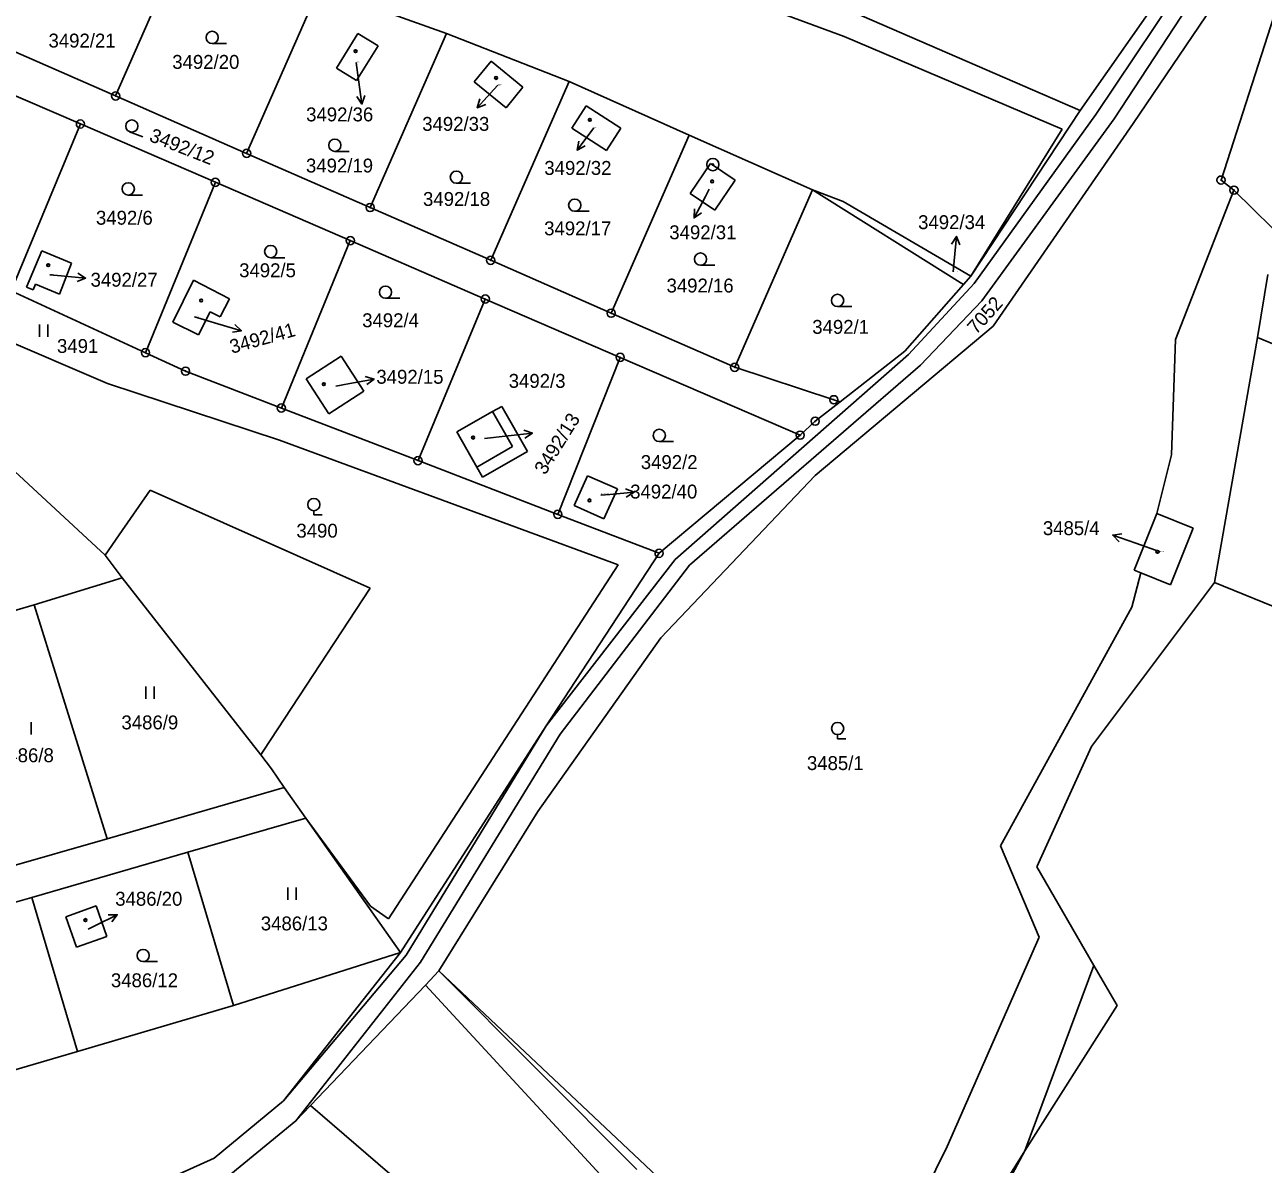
# Model space of a CAD drawing. Extents: x -593183 to -588034, y -1130415 to -1124994.
# Drawn here: x -592719.7 to -592568.1, y -1129131.8 to -1128992.3 of the extents above; entities that cross this region are included whole.
import ezdxf

# ---------------------------------------------------------------- set-up
doc = ezdxf.new("R2010")
doc.units = 0
for name, color, linetype in [('Vrstva 1', 7, 'Continuous'), ('Vrstva 16', 7, 'Continuous'), ('Vrstva 18', 7, 'Continuous'), ('Vrstva 19', 7, 'Continuous'), ('Vrstva 24', 7, 'Continuous'), ('Vrstva 25', 7, 'Continuous'), ('Vrstva 4', 7, 'Continuous')]:
    doc.layers.add(name, color=color, linetype=linetype)

msp = doc.modelspace()

# ---------------------------------------------------------------- linework, layer by layer
at = {"layer": 'Vrstva 1'}
for p, q in [((-592573.29, -1129011.33), (-592560.53, -1128971.61)), ((-592700.22, -1128981.88), (-592708.62, -1129001.03)), ((-592568.79, -1128981.77), (-592584.04, -1129004.42)), ((-592639.27, -1128986.41), (-592619.45, -1128993.77)), ((-592579.11, -1128986.5), (-592590.56, -1129002.83)), ((-592683.7, -1128987.81), (-592692.58, -1129008.06)), ((-592683.7, -1128987.81), (-592668.12, -1128993.38)), ((-592590.56, -1129002.83), (-592619.43, -1128990.29)), ((-592725.11, -1128993.8), (-592708.62, -1129001.03)), ((-592681.59, -1128997.61), (-592678.96, -1128993.4)), ((-592678.96, -1128993.4), (-592676.49, -1128994.89)), ((-592668.12, -1128993.38), (-592677.46, -1129014.69)), ((-592668.12, -1128993.38), (-592653.1, -1128999.25)), ((-592619.45, -1128993.77), (-592592.73, -1129005.09)), ((-592676.49, -1128994.89), (-592679.15, -1128999.14)), ((-592664.71, -1128999.29), (-592662.66, -1128996.78)), ((-592662.66, -1128996.78), (-592658.76, -1128999.97)), ((-592728.81, -1128997.59), (-592712.93, -1129004.46)), ((-592679.15, -1128999.14), (-592681.59, -1128997.61)), ((-592660.81, -1129002.48), (-592664.71, -1128999.29)), ((-592662.7, -1129021.15), (-592653.1, -1128999.25)), ((-592658.76, -1128999.97), (-592660.81, -1129002.48)), ((-592653.1, -1128999.25), (-592638.39, -1129005.81)), ((-592708.62, -1129001.03), (-592692.58, -1129008.06)), ((-592652.78, -1129004.97), (-592651.02, -1129002.24)), ((-592651.02, -1129002.24), (-592646.78, -1129004.98)), ((-592590.56, -1129002.83), (-592603.91, -1129023.08)), ((-592712.93, -1129004.46), (-592721.41, -1129024.9)), ((-592712.93, -1129004.46), (-592696.41, -1129011.6)), ((-592601.18, -1129029.23), (-592584.04, -1129004.42)), ((-592648.54, -1129007.71), (-592652.78, -1129004.97)), ((-592646.78, -1129004.98), (-592648.54, -1129007.71)), ((-592638.39, -1129005.81), (-592647.95, -1129027.62)), ((-592638.39, -1129005.81), (-592623.31, -1129012.53)), ((-592603.91, -1129023.08), (-592592.73, -1129005.09)), ((-592692.58, -1129008.06), (-592677.46, -1129014.69)), ((-592638.28, -1129012.98), (-592635.8, -1129009.3)), ((-592635.8, -1129009.3), (-592632.79, -1129011.33)), ((-592696.41, -1129011.6), (-592704.97, -1129032.46)), ((-592696.41, -1129011.6), (-592679.89, -1129018.74)), ((-592632.79, -1129011.33), (-592635.27, -1129015.01)), ((-592573.29, -1129011.33), (-592571.71, -1129012.56)), ((-592635.27, -1129015.01), (-592638.28, -1129012.98)), ((-592632.83, -1129034.25), (-592623.31, -1129012.53)), ((-592623.31, -1129012.53), (-592619.56, -1129013.97)), ((-592623.31, -1129012.53), (-592605.24, -1129023.85)), ((-592619.56, -1129013.97), (-592603.91, -1129023.08)), ((-592571.71, -1129012.56), (-592564.45, -1129019.72)), ((-592677.46, -1129014.69), (-592662.7, -1129021.15)), ((-592719.52, -1129024.44), (-592717.66, -1129019.99)), ((-592717.66, -1129019.99), (-592714.04, -1129021.5)), ((-592679.89, -1129018.74), (-592688.33, -1129039.23)), ((-592679.89, -1129018.74), (-592663.37, -1129025.89)), ((-592714.04, -1129021.5), (-592715.5, -1129025.29)), ((-592662.7, -1129021.15), (-592647.95, -1129027.62)), ((-592604.82, -1129024.11), (-592603.91, -1129023.08)), ((-592567.57, -1129022.9), (-592568.85, -1129030.58)), ((-592718.7, -1129024.78), (-592719.52, -1129024.44)), ((-592718.41, -1129024.08), (-592718.7, -1129024.78)), ((-592715.5, -1129025.29), (-592718.41, -1129024.08)), ((-592701.63, -1129028.71), (-592699.09, -1129023.6)), ((-592699.09, -1129023.6), (-592694.7, -1129025.87)), ((-592604.82, -1129024.11), (-592612.02, -1129032.27)), ((-592605.24, -1129023.85), (-592604.82, -1129024.11)), ((-592704.97, -1129032.46), (-592721.41, -1129024.9)), ((-592694.7, -1129025.87), (-592695.82, -1129028.08)), ((-592663.37, -1129025.89), (-592671.6, -1129045.67)), ((-592663.37, -1129025.89), (-592646.85, -1129033.03)), ((-592697.06, -1129027.46), (-592698.48, -1129030.29)), ((-592695.82, -1129028.08), (-592697.06, -1129027.46)), ((-592647.95, -1129027.62), (-592632.83, -1129034.25)), ((-592698.48, -1129030.29), (-592701.63, -1129028.71)), ((-592723.17, -1129030.44), (-592709.6, -1129036.24)), ((-592622.99, -1129047.5), (-592601.18, -1129029.23)), ((-592568.85, -1129030.58), (-592574.1, -1129060.59)), ((-592568.85, -1129030.58), (-592498.73, -1129059.92)), ((-592700.06, -1129034.72), (-592704.97, -1129032.46)), ((-592685.31, -1129035.67), (-592681.03, -1129032.87)), ((-592681.03, -1129032.87), (-592678.23, -1129037.15)), ((-592646.85, -1129033.03), (-592654.49, -1129052.25)), ((-592646.85, -1129033.03), (-592624.82, -1129042.56)), ((-592619.94, -1129038.47), (-592612.02, -1129032.27)), ((-592700.06, -1129034.72), (-592688.33, -1129039.23)), ((-592632.83, -1129034.25), (-592620.7, -1129038.22)), ((-592709.6, -1129036.24), (-592688.56, -1129043.17)), ((-592682.51, -1129039.95), (-592685.31, -1129035.67)), ((-592678.23, -1129037.15), (-592682.51, -1129039.95)), ((-592620.7, -1129038.22), (-592619.94, -1129038.47)), ((-592688.33, -1129039.23), (-592671.6, -1129045.67)), ((-592666.85, -1129042.15), (-592662.49, -1129039.67)), ((-592662.49, -1129039.67), (-592661.36, -1129039.03)), ((-592661.36, -1129039.03), (-592658.21, -1129044.56)), ((-592619.94, -1129038.47), (-592622.98, -1129040.85)), ((-592728.65, -1129039.91), (-592709.9, -1129057.25)), ((-592624.82, -1129042.56), (-592622.98, -1129040.85)), ((-592664.4, -1129046.46), (-592666.85, -1129042.15)), ((-592642.09, -1129057.02), (-592624.82, -1129042.56)), ((-592688.56, -1129043.17), (-592647.1, -1129058.41)), ((-592671.6, -1129045.67), (-592654.49, -1129052.25)), ((-592658.21, -1129044.56), (-592663.7, -1129047.68)), ((-592663.7, -1129047.68), (-592664.4, -1129046.46)), ((-592652.5, -1129051.15), (-592650.85, -1129047.52)), ((-592647.18, -1129049.13), (-592650.85, -1129047.52)), ((-592641.86, -1129067.36), (-592622.99, -1129047.5)), ((-592648.85, -1129052.8), (-592647.18, -1129049.13)), ((-592652.5, -1129051.15), (-592648.85, -1129052.8)), ((-592654.49, -1129052.25), (-592642.09, -1129057.02)), ((-592583.95, -1129059.08), (-592581.15, -1129052.15)), ((-592581.15, -1129052.15), (-592576.69, -1129053.95)), ((-592576.69, -1129053.95), (-592579.49, -1129060.88)), ((-592709.9, -1129057.25), (-592707.81, -1129060.01)), ((-592642.09, -1129057.02), (-592655.93, -1129078.12)), ((-592647.1, -1129058.41), (-592675.2, -1129101.76)), ((-592583.11, -1129059.42), (-592583.95, -1129059.08)), ((-592579.49, -1129060.88), (-592583.11, -1129059.42)), ((-592707.81, -1129060.01), (-592718.6, -1129063.31)), ((-592707.81, -1129060.01), (-592690.86, -1129081.7)), ((-592589.17, -1129080.66), (-592574.1, -1129060.59)), ((-592574.1, -1129060.59), (-592554.68, -1129068.54)), ((-592718.6, -1129063.31), (-592731.07, -1129067)), ((-592718.6, -1129063.31), (-592709.67, -1129091.97)), ((-592656.94, -1129088.63), (-592641.86, -1129067.36)), ((-592655.93, -1129078.12), (-592673.76, -1129105.9)), ((-592595.84, -1129095.4), (-592589.17, -1129080.66)), ((-592690.86, -1129081.7), (-592689.53, -1129083.41)), ((-592687.99, -1129085.67), (-592689.53, -1129083.41)), ((-592687.99, -1129085.67), (-592709.67, -1129091.97)), ((-592685.35, -1129089.43), (-592687.99, -1129085.67)), ((-592699.8, -1129093.61), (-592685.35, -1129089.43)), ((-592673.76, -1129105.9), (-592685.35, -1129089.43)), ((-592685.35, -1129089.43), (-592677.42, -1129100.23)), ((-592669.04, -1129108.14), (-592656.94, -1129088.63)), ((-592709.67, -1129091.97), (-592722.19, -1129095.57)), ((-592699.8, -1129093.61), (-592718.88, -1129099.14)), ((-592694.19, -1129112.37), (-592699.8, -1129093.61)), ((-592595.84, -1129095.4), (-592588.85, -1129107.46)), ((-592718.88, -1129099.14), (-592738.2, -1129104.7)), ((-592718.88, -1129099.14), (-592713.27, -1129118.02)), ((-592714.73, -1129101.51), (-592711, -1129100.19)), ((-592711, -1129100.19), (-592709.68, -1129103.92)), ((-592675.2, -1129101.76), (-592677.42, -1129100.23)), ((-592713.41, -1129105.24), (-592714.73, -1129101.51)), ((-592709.68, -1129103.92), (-592713.41, -1129105.24)), ((-592694.19, -1129112.37), (-592673.76, -1129105.9)), ((-592673.76, -1129105.9), (-592688.05, -1129124.05)), ((-592588.85, -1129107.46), (-592597.31, -1129130.16)), ((-592669.04, -1129108.14), (-592670.69, -1129109.87)), ((-592669.04, -1129108.14), (-592619.36, -1129154.88)), ((-592684.77, -1129124.62), (-592670.69, -1129109.87)), ((-592670.69, -1129109.87), (-592647.33, -1129135.19)), ((-592713.27, -1129118.02), (-592694.19, -1129112.37)), ((-592732.76, -1129123.67), (-592713.27, -1129118.02)), ((-592688.05, -1129124.05), (-592696.54, -1129131.05)), ((-592686.57, -1129126.51), (-592684.77, -1129124.62)), ((-592684.77, -1129124.62), (-592650.74, -1129153.85)), ((-592694.96, -1129133.39), (-592686.57, -1129126.51)), ((-592597.31, -1129130.16), (-592613.56, -1129160.33)), ((-592696.54, -1129131.05), (-592715.63, -1129139.64))]:
    msp.add_line(p, q, dxfattribs=at)
at = {"layer": 'Vrstva 16'}
for p, q in [((-592679.18, -1128996.92), (-592678.88, -1128999.05)), ((-592661.84, -1128999.72), (-592662.33, -1129000.25)), ((-592650.09, -1129004.92), (-592650.33, -1129005.24)), ((-592635.95, -1129012.46), (-592636.4, -1129013.32)), ((-592606.07, -1129022.54), (-592605.96, -1129021.22)), ((-592716.68, -1129022.94), (-592715.28, -1129023.06)), ((-592698.98, -1129028.05), (-592696.1, -1129028.91)), ((-592681.66, -1129036.56), (-592679.94, -1129036.24)), ((-592663.45, -1129042.97), (-592660.58, -1129042.65)), ((-592649.21, -1129049.89), (-592648.14, -1129049.8)), ((-592580.74, -1129056.84), (-592583.72, -1129055.79)), ((-592712, -1129103.05), (-592711.1, -1129102.6))]:
    msp.add_line(p, q, dxfattribs=at)
at = {"layer": 'Vrstva 24'}
for centre, radius in [((-592708.62, -1129001.03), 0.5), ((-592708.62, -1129001.03), 0.0327), ((-592712.93, -1129004.46), 0.5), ((-592712.93, -1129004.46), 0.0327), ((-592692.58, -1129008.06), 0.5), ((-592692.58, -1129008.06), 0.0327), ((-592635.51, -1129009.43), 0.75), ((-592635.51, -1129009.43), 0.0903), ((-592573.29, -1129011.33), 0.5), ((-592696.41, -1129011.6), 0.5), ((-592696.41, -1129011.6), 0.0327), ((-592573.29, -1129011.33), 0.0327), ((-592571.71, -1129012.56), 0.5), ((-592571.71, -1129012.56), 0.0327), ((-592677.46, -1129014.69), 0.5), ((-592677.46, -1129014.69), 0.0327), ((-592679.89, -1129018.74), 0.5), ((-592679.89, -1129018.74), 0.0327), ((-592662.7, -1129021.15), 0.5), ((-592662.7, -1129021.15), 0.0327), ((-592663.37, -1129025.89), 0.5), ((-592663.37, -1129025.89), 0.0327), ((-592647.95, -1129027.62), 0.5), ((-592647.95, -1129027.62), 0.0327), ((-592704.97, -1129032.46), 0.5), ((-592704.97, -1129032.46), 0.0327), ((-592646.85, -1129033.03), 0.5), ((-592646.85, -1129033.03), 0.0327), ((-592700.06, -1129034.72), 0.5), ((-592700.06, -1129034.72), 0.0327), ((-592632.83, -1129034.25), 0.5), ((-592632.83, -1129034.25), 0.0327), ((-592620.7, -1129038.22), 0.5), ((-592620.7, -1129038.22), 0.0327), ((-592688.33, -1129039.23), 0.5), ((-592688.33, -1129039.23), 0.0327), ((-592622.98, -1129040.85), 0.5), ((-592622.98, -1129040.85), 0.0327), ((-592624.82, -1129042.56), 0.5), ((-592624.82, -1129042.56), 0.0327), ((-592671.6, -1129045.67), 0.5), ((-592671.6, -1129045.67), 0.0327), ((-592654.49, -1129052.25), 0.5), ((-592654.49, -1129052.25), 0.0327), ((-592642.09, -1129057.02), 0.5), ((-592642.09, -1129057.02), 0.0327)]:
    msp.add_circle(centre, radius, dxfattribs=at)
at = {"layer": 'Vrstva 25'}
for p, q in [((-592695.05, -1128994.61), (-592696.8, -1128994.61)), ((-592678.88, -1128999.05), (-592678.47, -1129002.02)), ((-592662.33, -1129000.25), (-592664.35, -1129002.47)), ((-592705.28, -1129006.05), (-592706.91, -1129005.41)), ((-592650.33, -1129005.24), (-592652.12, -1129007.65)), ((-592680.04, -1129007.82), (-592681.79, -1129007.82)), ((-592665.16, -1129011.72), (-592666.91, -1129011.72)), ((-592705.32, -1129013.16), (-592707.07, -1129013.16)), ((-592636.4, -1129013.32), (-592637.8, -1129015.97)), ((-592650.67, -1129015.15), (-592652.42, -1129015.15)), ((-592605.96, -1129021.22), (-592605.7, -1129018.23)), ((-592687.89, -1129020.83), (-592689.64, -1129020.83)), ((-592715.28, -1129023.06), (-592712.29, -1129023.32)), ((-592635.27, -1129021.75), (-592637.02, -1129021.75)), ((-592673.83, -1129025.8), (-592675.58, -1129025.8)), ((-592618.49, -1129026.81), (-592620.24, -1129026.81)), ((-592717.96, -1129029), (-592717.96, -1129030.5)), ((-592716.94, -1129030.5), (-592716.94, -1129029)), ((-592696.1, -1129028.91), (-592693.23, -1129029.77)), ((-592679.94, -1129036.24), (-592676.99, -1129035.68)), ((-592660.58, -1129042.65), (-592657.6, -1129042.31)), ((-592640.31, -1129043.33), (-592642.06, -1129043.33)), ((-592648.14, -1129049.8), (-592645.15, -1129049.54)), ((-592684.36, -1129051.81), (-592684.36, -1129052.31)), ((-592684.36, -1129052.31), (-592683.34, -1129052.31)), ((-592583.72, -1129055.79), (-592586.55, -1129054.79)), ((-592704.92, -1129073.32), (-592704.92, -1129074.82)), ((-592703.9, -1129074.82), (-592703.9, -1129073.32)), ((-592718.96, -1129079.18), (-592718.96, -1129077.68)), ((-592620.23, -1129079.22), (-592620.23, -1129079.72)), ((-592620.23, -1129079.72), (-592619.21, -1129079.72)), ((-592687.53, -1129097.93), (-592687.53, -1129099.43)), ((-592686.51, -1129099.43), (-592686.51, -1129097.93)), ((-592711.1, -1129102.6), (-592708.42, -1129101.26)), ((-592703.5, -1129107), (-592705.25, -1129107))]:
    msp.add_line(p, q, dxfattribs=at)
for points in [[(-592678.11, -1129000.96), (-592678.47, -1129002.02), (-592679.1, -1129001.1)], [(-592663.31, -1129002.06), (-592664.35, -1129002.47), (-592664.05, -1129001.39)], [(-592651.12, -1129007.14), (-592652.12, -1129007.65), (-592651.92, -1129006.55)], [(-592636.89, -1129015.32), (-592637.8, -1129015.97), (-592637.77, -1129014.86)], [(-592606.29, -1129019.18), (-592605.7, -1129018.23), (-592605.29, -1129019.27)], [(-592713.24, -1129022.73), (-592712.29, -1129023.32), (-592713.33, -1129023.73)], [(-592694.04, -1129029), (-592693.23, -1129029.77), (-592694.33, -1129029.96)], [(-592678.07, -1129035.38), (-592676.99, -1129035.68), (-592677.88, -1129036.36)], [(-592658.65, -1129041.93), (-592657.6, -1129042.31), (-592658.54, -1129042.92)], [(-592646.19, -1129049.13), (-592645.15, -1129049.54), (-592646.1, -1129050.13)], [(-592585.77, -1129055.6), (-592586.55, -1129054.79), (-592585.44, -1129054.65)], [(-592709.53, -1129101.26), (-592708.42, -1129101.26), (-592709.09, -1129102.15)]]:
    msp.add_lwpolyline(points, dxfattribs=at)
for centre, radius in [((-592696.8, -1128993.86), 0.75), ((-592679.24, -1128995.55), 0.175), ((-592679.24, -1128995.55), 0.15), ((-592662.05, -1128998.83), 0.175), ((-592662.05, -1128998.83), 0.15), ((-592706.64, -1129004.71), 0.75), ((-592650.56, -1129003.96), 0.175), ((-592650.56, -1129003.96), 0.15), ((-592681.79, -1129007.07), 0.75), ((-592666.91, -1129010.97), 0.75), ((-592707.07, -1129012.41), 0.75), ((-592635.59, -1129011.49), 0.175), ((-592635.59, -1129011.49), 0.15), ((-592652.42, -1129014.4), 0.75), ((-592689.64, -1129020.08), 0.75), ((-592637.02, -1129021), 0.75), ((-592716.87, -1129021.75), 0.175), ((-592716.87, -1129021.75), 0.15), ((-592675.58, -1129025.05), 0.75), ((-592698.15, -1129026.07), 0.175), ((-592698.15, -1129026.07), 0.15), ((-592620.24, -1129026.06), 0.75), ((-592683.14, -1129036.31), 0.175), ((-592683.14, -1129036.31), 0.15), ((-592664.86, -1129042.85), 0.175), ((-592664.86, -1129042.85), 0.15), ((-592642.06, -1129042.58), 0.75), ((-592684.36, -1129051.06), 0.75), ((-592650.61, -1129050.54), 0.175), ((-592650.61, -1129050.54), 0.15), ((-592581.09, -1129056.84), 0.175), ((-592581.09, -1129056.84), 0.15), ((-592620.23, -1129078.47), 0.75), ((-592712.32, -1129101.92), 0.175), ((-592712.32, -1129101.92), 0.15), ((-592705.25, -1129106.25), 0.75)]:
    msp.add_circle(centre, radius, dxfattribs=at)
at = {"layer": 'Vrstva 4'}
for p, q in [((-592575.74, -1128984.03), (-592588.62, -1129003.3)), ((-592573.87, -1128984.74), (-592586.38, -1129003.85)), ((-592588.62, -1129003.3), (-592603.5, -1129024)), ((-592586.38, -1129003.85), (-592602.56, -1129026.13)), ((-592571.71, -1129012.56), (-592578.85, -1129030.84)), ((-592603.5, -1129024), (-592611.57, -1129032.67)), ((-592602.56, -1129026.13), (-592610.07, -1129033.99)), ((-592578.85, -1129030.84), (-592579.35, -1129044.96)), ((-592611.57, -1129032.67), (-592640.14, -1129057.79)), ((-592610.07, -1129033.99), (-592638.37, -1129058.49)), ((-592662.49, -1129039.67), (-592660.05, -1129043.96)), ((-592660.05, -1129043.96), (-592664.4, -1129046.46)), ((-592579.35, -1129044.96), (-592581.15, -1129052.15)), ((-592704.41, -1129049.29), (-592708.19, -1129054.77)), ((-592704.41, -1129049.29), (-592677.46, -1129061.29)), ((-592709.9, -1129057.25), (-592708.19, -1129054.77)), ((-592640.14, -1129057.79), (-592655.93, -1129078.12)), ((-592638.37, -1129058.49), (-592654.22, -1129079.16)), ((-592584.2, -1129063.6), (-592583.11, -1129059.42)), ((-592690.57, -1129081.26), (-592677.46, -1129061.29)), ((-592600.31, -1129092.84), (-592584.2, -1129063.6)), ((-592655.93, -1129078.12), (-592673.06, -1129106.23)), ((-592671.3, -1129107.07), (-592654.22, -1129079.16)), ((-592690.86, -1129081.7), (-592690.57, -1129081.26)), ((-592600.31, -1129092.84), (-592595.57, -1129104.01)), ((-592595.57, -1129104.01), (-592606.83, -1129129.63)), ((-592673.06, -1129106.23), (-592688.05, -1129124.05)), ((-592686.57, -1129126.51), (-592671.3, -1129107.07)), ((-592588.85, -1129107.46), (-592586.01, -1129112.36)), ((-592669.04, -1129108.14), (-592644.82, -1129132.47)), ((-592586.01, -1129112.36), (-592597.31, -1129130.16)), ((-592606.83, -1129129.63), (-592619.36, -1129154.88)), ((-592597.31, -1129130.16), (-592609.66, -1129149.93))]:
    msp.add_line(p, q, dxfattribs=at)

# ---------------------------------------------------------------- texts
at = {"layer": 'Vrstva 16'}
for s, p in [('3492/36', (-592685.3, -1129004.14)), ('3492/33', (-592671.09, -1129005.3)), ('3492/32', (-592656.14, -1129010.69)), ('3492/31', (-592640.84, -1129018.57)), ('3492/34', (-592610.38, -1129017.33)), ('3492/27', (-592711.69, -1129024.38)), ('3492/15', (-592676.7, -1129036.26)), ('3492/40', (-592645.63, -1129050.31)), ('3485/4', (-592595.11, -1129054.79)), ('3486/20', (-592708.67, -1129100.16))]:
    msp.add_text(s, height=1.7, dxfattribs=at).set_placement(p)
for s, rotation, p in [('3492/41', 15.6423, (-592694.39, -1129032.6)), ('3492/13', 58.0201, (-592656.04, -1129047.52))]:
    msp.add_text(s, height=1.7, rotation=rotation, dxfattribs=at).set_placement(p)
at = {"layer": 'Vrstva 18'}
for s, height, p in [('3492/21', 1.7, (-592716.84, -1128995.1)), ('3492/20', 1.7, (-592701.69, -1128997.71)), ('3492/19', 1.7, (-592685.32, -1129010.4)), ('3492/18', 1.7, (-592670.99, -1129014.49)), ('3492/6', 1.7, (-592711.03, -1129016.79)), ('3492/17', 1.7, (-592656.16, -1129018.09)), ('3492/5', 1.7, (-592693.5, -1129023.22)), ('3492/34', 0.1, (-592606.07, -1129022.54)), ('3492/16', 1.7, (-592641.18, -1129025.09)), ('3492/4', 1.7, (-592678.44, -1129029.34)), ('3492/1', 1.7, (-592623.34, -1129030.15)), ('3491', 1.7, (-592715.8, -1129032.49)), ('3492/3', 1.7, (-592660.5, -1129036.76)), ('3492/2', 1.7, (-592644.33, -1129046.7)), ('3490', 1.7, (-592686.49, -1129055.1)), ('3486/9', 1.7, (-592707.91, -1129078.57)), ('3486/8', 1.7, (-592723.14, -1129082.59)), ('3485/1', 1.7, (-592623.99, -1129083.55)), ('3486/13', 1.7, (-592690.85, -1129103.18)), ('3486/12', 1.7, (-592709.2, -1129110.14))]:
    msp.add_text(s, height=height, dxfattribs=at).set_placement(p)
for s, rotation, p in [('3492/12', 338.5523, (-592704.62, -1129006.51)), ('7052', 48.1864, (-592603.26, -1129030.3))]:
    msp.add_text(s, height=1.7, rotation=rotation, dxfattribs=at).set_placement(p)
at = {"layer": 'Vrstva 19'}
for s, height, p in [('3492/36', 0.1, (-592679.18, -1128996.92)), ('3492/33', 0.1, (-592661.84, -1128999.72)), ('3492/32', 0.1, (-592650.09, -1129004.92)), ('3492/31', 0.1, (-592635.95, -1129012.46)), ('3492/27', 0.1, (-592716.68, -1129022.94)), ('3492/41', 0.1, (-592698.98, -1129028.05)), ('3492/15', 0.1, (-592681.66, -1129036.56)), ('3492/13', 0.1, (-592663.45, -1129042.97)), ('3492/40', 0.2, (-592649.21, -1129049.89)), ('3485/4', 0.1, (-592580.74, -1129056.84)), ('3486/20', 0.1, (-592712, -1129103.05))]:
    msp.add_text(s, height=height, dxfattribs=at).set_placement(p)

doc.saveas('drawing.dxf')
